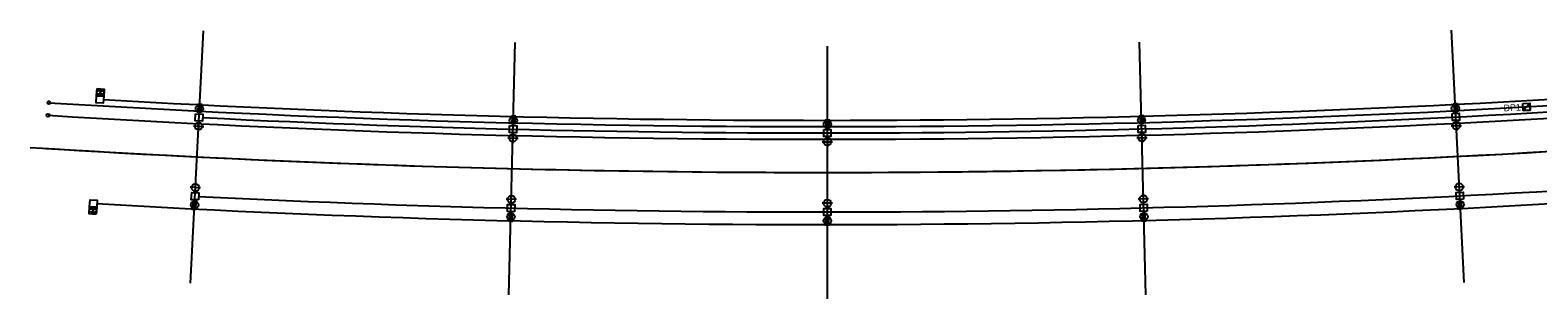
# Model space of a CAD drawing. Extents: x 927222 to 928611, y 636651 to 637029.
# Drawn here: x 927221.8 to 927460.9, y 636666.9 to 636709.5 of the extents above; entities that cross this region are included whole.
import ezdxf

# ---------------------------------------------------------------- set-up
doc = ezdxf.new("R2010")
doc.units = 0
for name, color, linetype in [('Miscellaneous2', 7, 'Continuous'), ('NonPlottingEle_dp', 7, 'Continuous'), ('PoleLight', 7, 'Continuous'), ('TextLabel', 7, 'Continuous')]:
    doc.layers.add(name, color=color, linetype=linetype)

msp = doc.modelspace()

# ---------------------------------------------------------------- linework, layer by layer
at = {"layer": 'Miscellaneous2'}
for p, q in [((927247.3, 636669.45), (927249.32, 636709.39)), ((927449.22, 636669.52), (927447.23, 636709.47)), ((927297.76, 636667.56), (927298.78, 636707.55)), ((927348.26, 636666.95), (927348.27, 636706.95)), ((927398.75, 636667.6), (927397.77, 636707.59))]:
    msp.add_line(p, q, dxfattribs=at)
for start in [266.38424, 266.45613]:
    msp.add_arc((927347.51, 638679.45), 1992.5, start, 273.54621, dxfattribs=at)
at = {"layer": 'NonPlottingEle_dp'}
for radius, start in [(1984.25, 266.70547), (1985.25, 266.45639), (1986.25, 267.16262), (1987.25, 266.45632), (1998.75, 267.16225), (2000.75, 266.70281)]:
    msp.add_arc((927347.51, 638679.45), radius, start, 273.54621, dxfattribs=at)
at = {"layer": 'PoleLight'}
for p, q in [((927248.51, 636697.88), (927248.44, 636696.5)), ((927248.65, 636696.22), (927248.66, 636696.45)), ((927248.96, 636697.85), (927248.89, 636696.48)), ((927447.58, 636697.93), (927447.64, 636696.56)), ((927447.88, 636696.3), (927447.87, 636696.52)), ((927448.03, 636697.95), (927448.09, 636696.58)), ((927247.73, 636694.32), (927249.37, 636694.24)), ((927248.59, 636695.1), (927248.51, 636693.46)), ((927298.26, 636696.02), (927298.23, 636694.64)), ((927298.44, 636694.37), (927298.45, 636694.59)), ((927298.71, 636696), (927298.68, 636694.63)), ((927348.04, 636695.4), (927348.04, 636694.03)), ((927348.27, 636693.76), (927348.27, 636693.99)), ((927348.49, 636695.4), (927348.49, 636694.03)), ((927397.83, 636696.04), (927397.86, 636694.67)), ((927398.09, 636694.41), (927398.09, 636694.63)), ((927398.28, 636696.05), (927398.31, 636694.68)), ((927447.16, 636694.31), (927448.8, 636694.4)), ((927447.94, 636695.18), (927448.02, 636693.54)), ((927297.57, 636692.44), (927299.22, 636692.4)), ((927298.41, 636693.24), (927298.37, 636691.6)), ((927347.45, 636691.82), (927349.09, 636691.81)), ((927348.27, 636692.64), (927348.27, 636690.99)), ((927397.32, 636692.44), (927398.96, 636692.48)), ((927398.12, 636693.28), (927398.16, 636691.64)), ((927248.88, 636684.52), (927247.24, 636684.6)), ((927248.02, 636683.74), (927248.1, 636685.38)), ((927449.28, 636684.68), (927447.64, 636684.6)), ((927448.51, 636683.82), (927448.42, 636685.46)), ((927247.65, 636680.99), (927247.72, 636682.36)), ((927247.96, 636682.62), (927247.95, 636682.39)), ((927248.1, 636680.96), (927248.17, 636682.34)), ((927298.97, 636682.67), (927297.32, 636682.71)), ((927298.13, 636681.87), (927298.17, 636683.51)), ((927349.08, 636682.08), (927347.44, 636682.08)), ((927348.26, 636681.26), (927348.26, 636682.9)), ((927399.2, 636682.75), (927397.56, 636682.71)), ((927398.4, 636681.91), (927398.36, 636683.55)), ((927448.42, 636681.04), (927448.35, 636682.41)), ((927448.56, 636682.69), (927448.57, 636682.47)), ((927448.87, 636681.06), (927448.8, 636682.43)), ((927297.83, 636679.11), (927297.86, 636680.48)), ((927298.1, 636680.75), (927298.09, 636680.52)), ((927298.28, 636679.1), (927298.31, 636680.47)), ((927348.04, 636678.49), (927348.04, 636679.87)), ((927348.26, 636680.14), (927348.26, 636679.91)), ((927348.49, 636678.49), (927348.49, 636679.87)), ((927398.24, 636679.14), (927398.21, 636680.51)), ((927398.43, 636680.78), (927398.43, 636680.56)), ((927398.69, 636679.15), (927398.66, 636680.52))]:
    msp.add_line(p, q, dxfattribs=at)
for centre, radius in [((927224.8, 636697.99), 0.236), ((927248.69, 636697.04), 0.597), ((927447.84, 636697.12), 0.597), ((927224.67, 636696), 0.236), ((927248.55, 636694.28), 0.597), ((927298.46, 636695.19), 0.597), ((927348.27, 636694.58), 0.597), ((927398.07, 636695.23), 0.597), ((927447.98, 636694.36), 0.597), ((927298.39, 636692.42), 0.597), ((927348.27, 636691.81), 0.597), ((927398.14, 636692.46), 0.597), ((927248.06, 636684.56), 0.597), ((927448.46, 636684.64), 0.597), ((927247.92, 636681.8), 0.597), ((927298.15, 636682.69), 0.597), ((927348.26, 636682.08), 0.597), ((927398.38, 636682.73), 0.597), ((927448.6, 636681.87), 0.597), ((927298.08, 636679.93), 0.597), ((927348.26, 636679.31), 0.597), ((927398.45, 636679.96), 0.597)]:
    msp.add_circle(centre, radius, dxfattribs=at)
at = {"layer": 'TextLabel'}
for p, q in [((927458.6, 636696.75), (927459.66, 636697.93)), ((927459.66, 636697.93), (927458.6, 636696.75))]:
    msp.add_line(p, q, dxfattribs=at)
for points in [[(927232.38, 636699.1), (927233.51, 636699.04), (927233.44, 636697.92), (927232.32, 636697.98)], [(927232.45, 636700.23), (927233.01, 636700.2), (927232.94, 636699.07), (927232.38, 636699.1)], [(927233.01, 636700.2), (927233.57, 636700.16), (927233.51, 636699.04), (927232.94, 636699.07)], [(927447.32, 636696.27), (927448.44, 636696.33), (927448.5, 636695.2), (927447.38, 636695.15)], [(927458.54, 636697.87), (927459.66, 636697.93), (927459.72, 636696.81), (927458.6, 636696.75)], [(927248.09, 636696.25), (927249.21, 636696.2), (927249.16, 636695.07), (927248.03, 636695.13)], [(927297.88, 636694.38), (927299.01, 636694.35), (927298.98, 636693.23), (927297.85, 636693.26)], [(927397.53, 636694.39), (927398.65, 636694.42), (927398.68, 636693.3), (927397.56, 636693.27)], [(927347.71, 636693.76), (927348.83, 636693.76), (927348.83, 636692.64), (927347.7, 636692.64)], [(927232.4, 636681.45), (927231.28, 636681.51), (927231.34, 636682.64), (927232.47, 636682.57)], [(927248.52, 636682.59), (927247.4, 636682.64), (927247.46, 636683.77), (927248.58, 636683.71)], [(927449.12, 636682.72), (927448, 636682.66), (927447.94, 636683.79), (927449.07, 636683.84)], [(927231.77, 636680.36), (927231.21, 636680.39), (927231.28, 636681.51), (927231.84, 636681.48)], [(927232.33, 636680.33), (927231.77, 636680.36), (927231.84, 636681.48), (927232.4, 636681.45)], [(927298.66, 636680.73), (927297.53, 636680.76), (927297.56, 636681.89), (927298.69, 636681.86)], [(927348.82, 636680.14), (927347.7, 636680.14), (927347.7, 636681.26), (927348.83, 636681.26)], [(927398.99, 636680.8), (927397.87, 636680.77), (927397.84, 636681.9), (927398.96, 636681.92)]]:
    msp.add_lwpolyline(points, close=True, dxfattribs=at)
msp.add_lwpolyline([(927458.6, 636696.75), (927459.72, 636696.81), (927459.66, 636697.93)], dxfattribs=at)
for centre in [(927232.7, 636699.65), (927233.26, 636699.62), (927231.53, 636680.94), (927232.09, 636680.9)]:
    msp.add_circle(centre, 0.281, dxfattribs=at)

# ---------------------------------------------------------------- texts
msp.add_text('DP1', height=1.05, rotation=3.1943, dxfattribs=at).set_placement((927455.52, 636696.61))

doc.saveas('drawing.dxf')
